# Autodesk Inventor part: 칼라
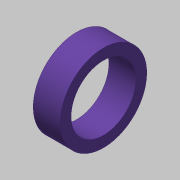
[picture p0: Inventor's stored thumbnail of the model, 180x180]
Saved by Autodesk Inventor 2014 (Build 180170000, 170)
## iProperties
Created: 2020-04
Part Number: 칼라
Material: 강철, 연강
Document SubType Name: Modeling
Designer: mduedu
Density: 7.86 g/cm^3
Appearance: 보라색
Mass: 3.45701 g
Surface Area: 6.15752 cm^2
Volume: 0.439823 cm^3
Author: mduedu
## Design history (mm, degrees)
sketch "스케치1"
  geometry: C1 r 8 at (0, 0); C2 r 6 at (0, 0); 1 further point
  constraints: 2 centre point, 2 coincident
  dimensions: "d0" = 16 diameter of C1; "d1" = 12 diameter of C2
extrude "돌출1" new body sketch "스케치1" distance "d2" = 5; taper "d3" = 0 deg
node "솔리드1"
